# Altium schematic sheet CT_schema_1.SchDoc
size 684 x 556 mm
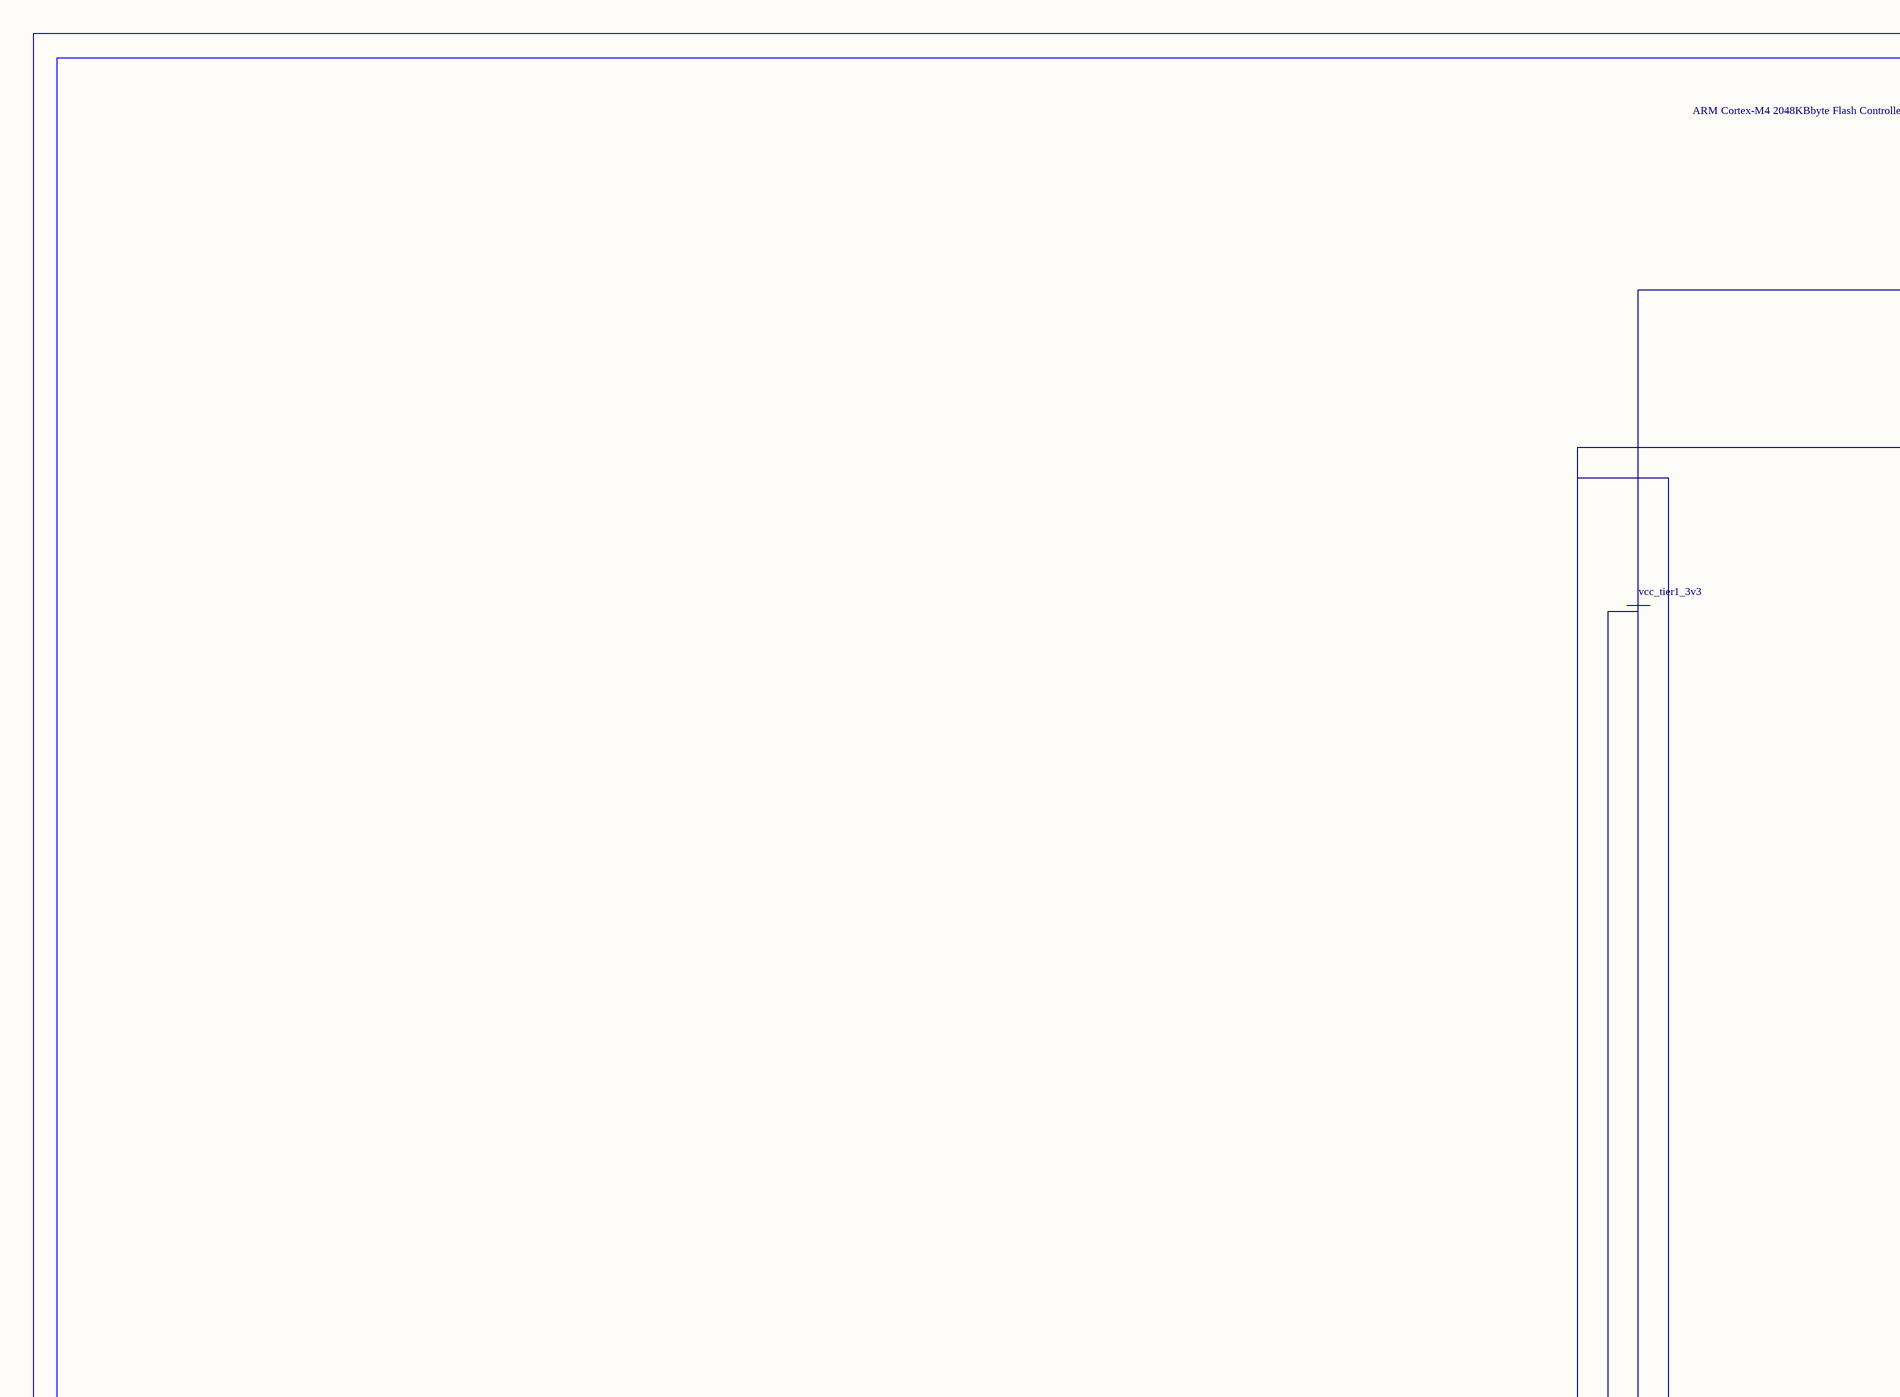
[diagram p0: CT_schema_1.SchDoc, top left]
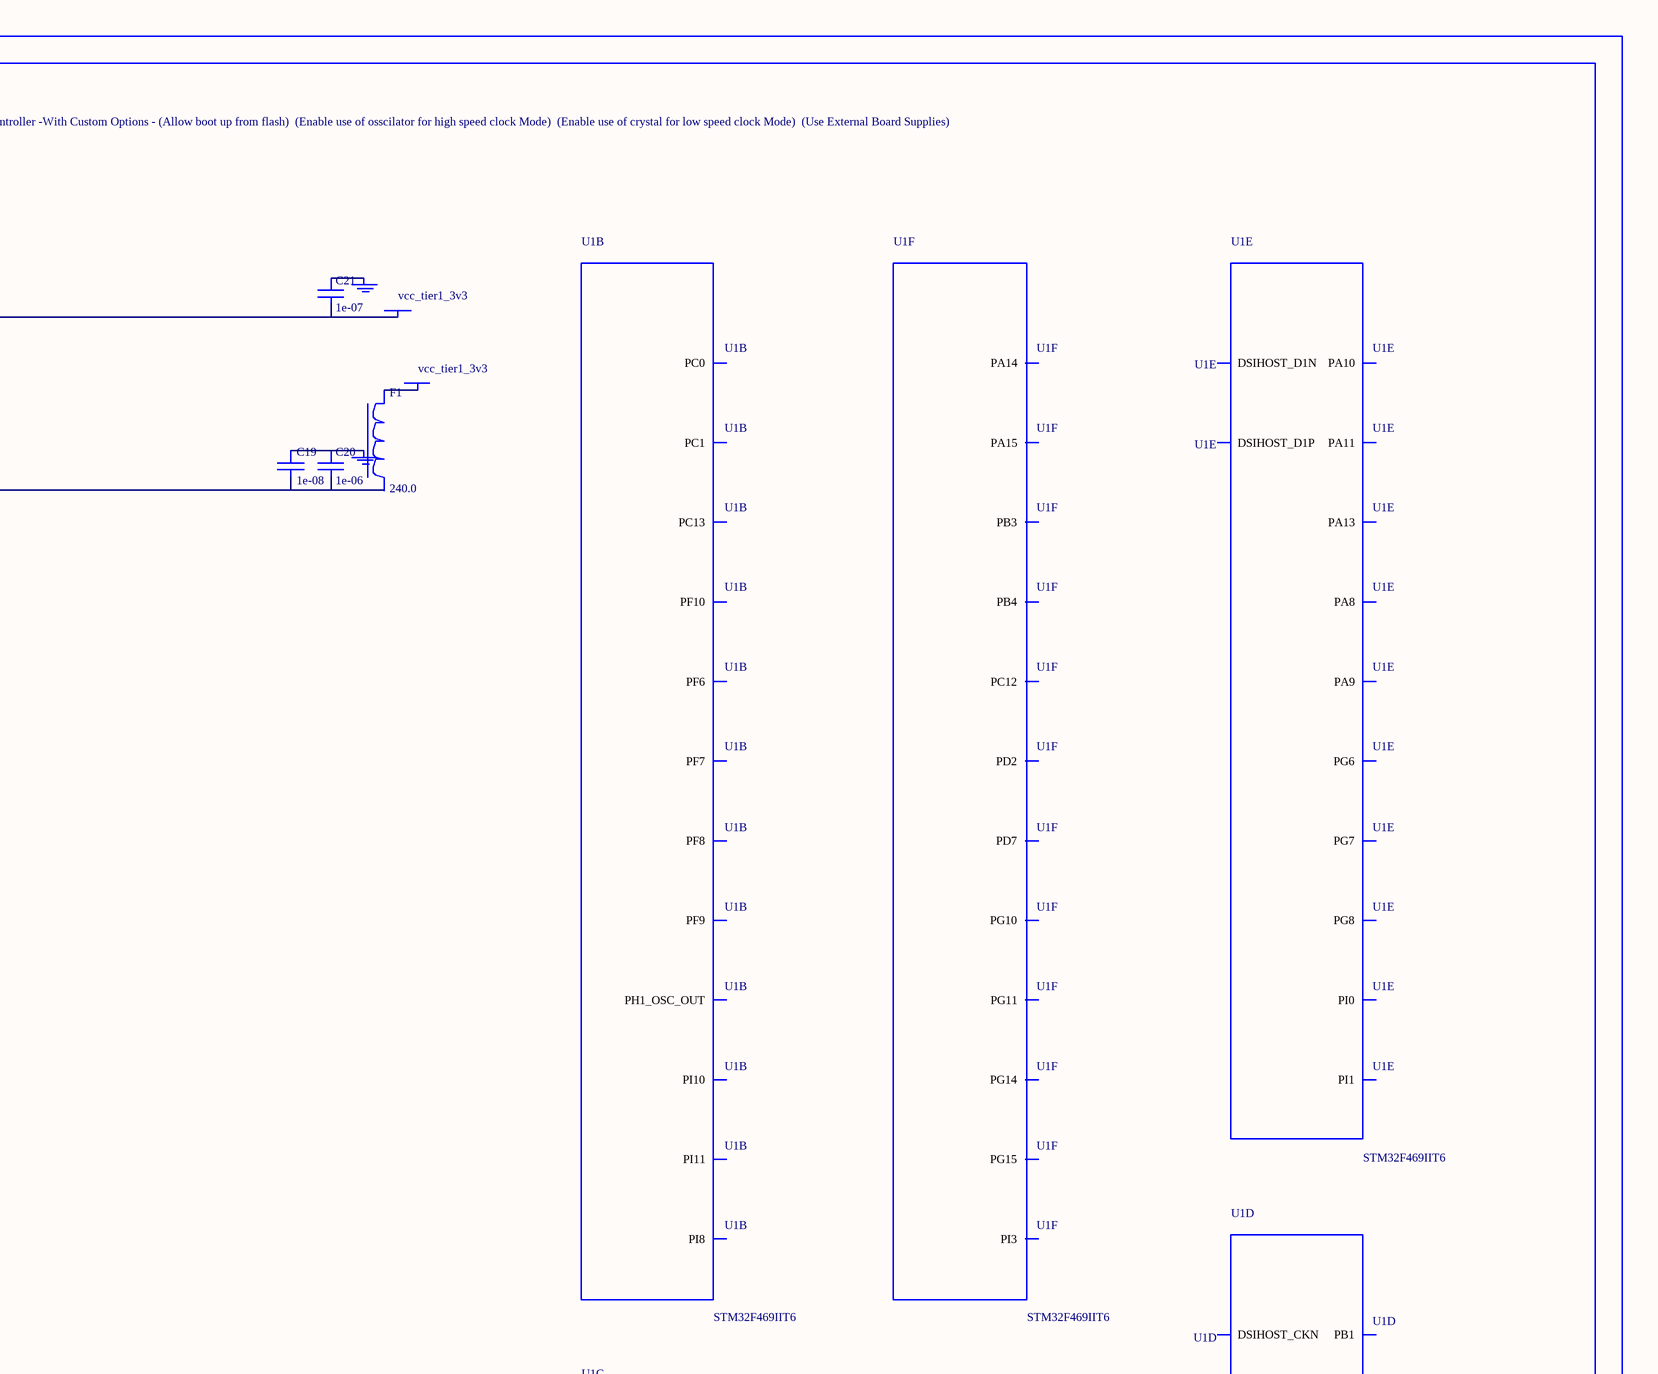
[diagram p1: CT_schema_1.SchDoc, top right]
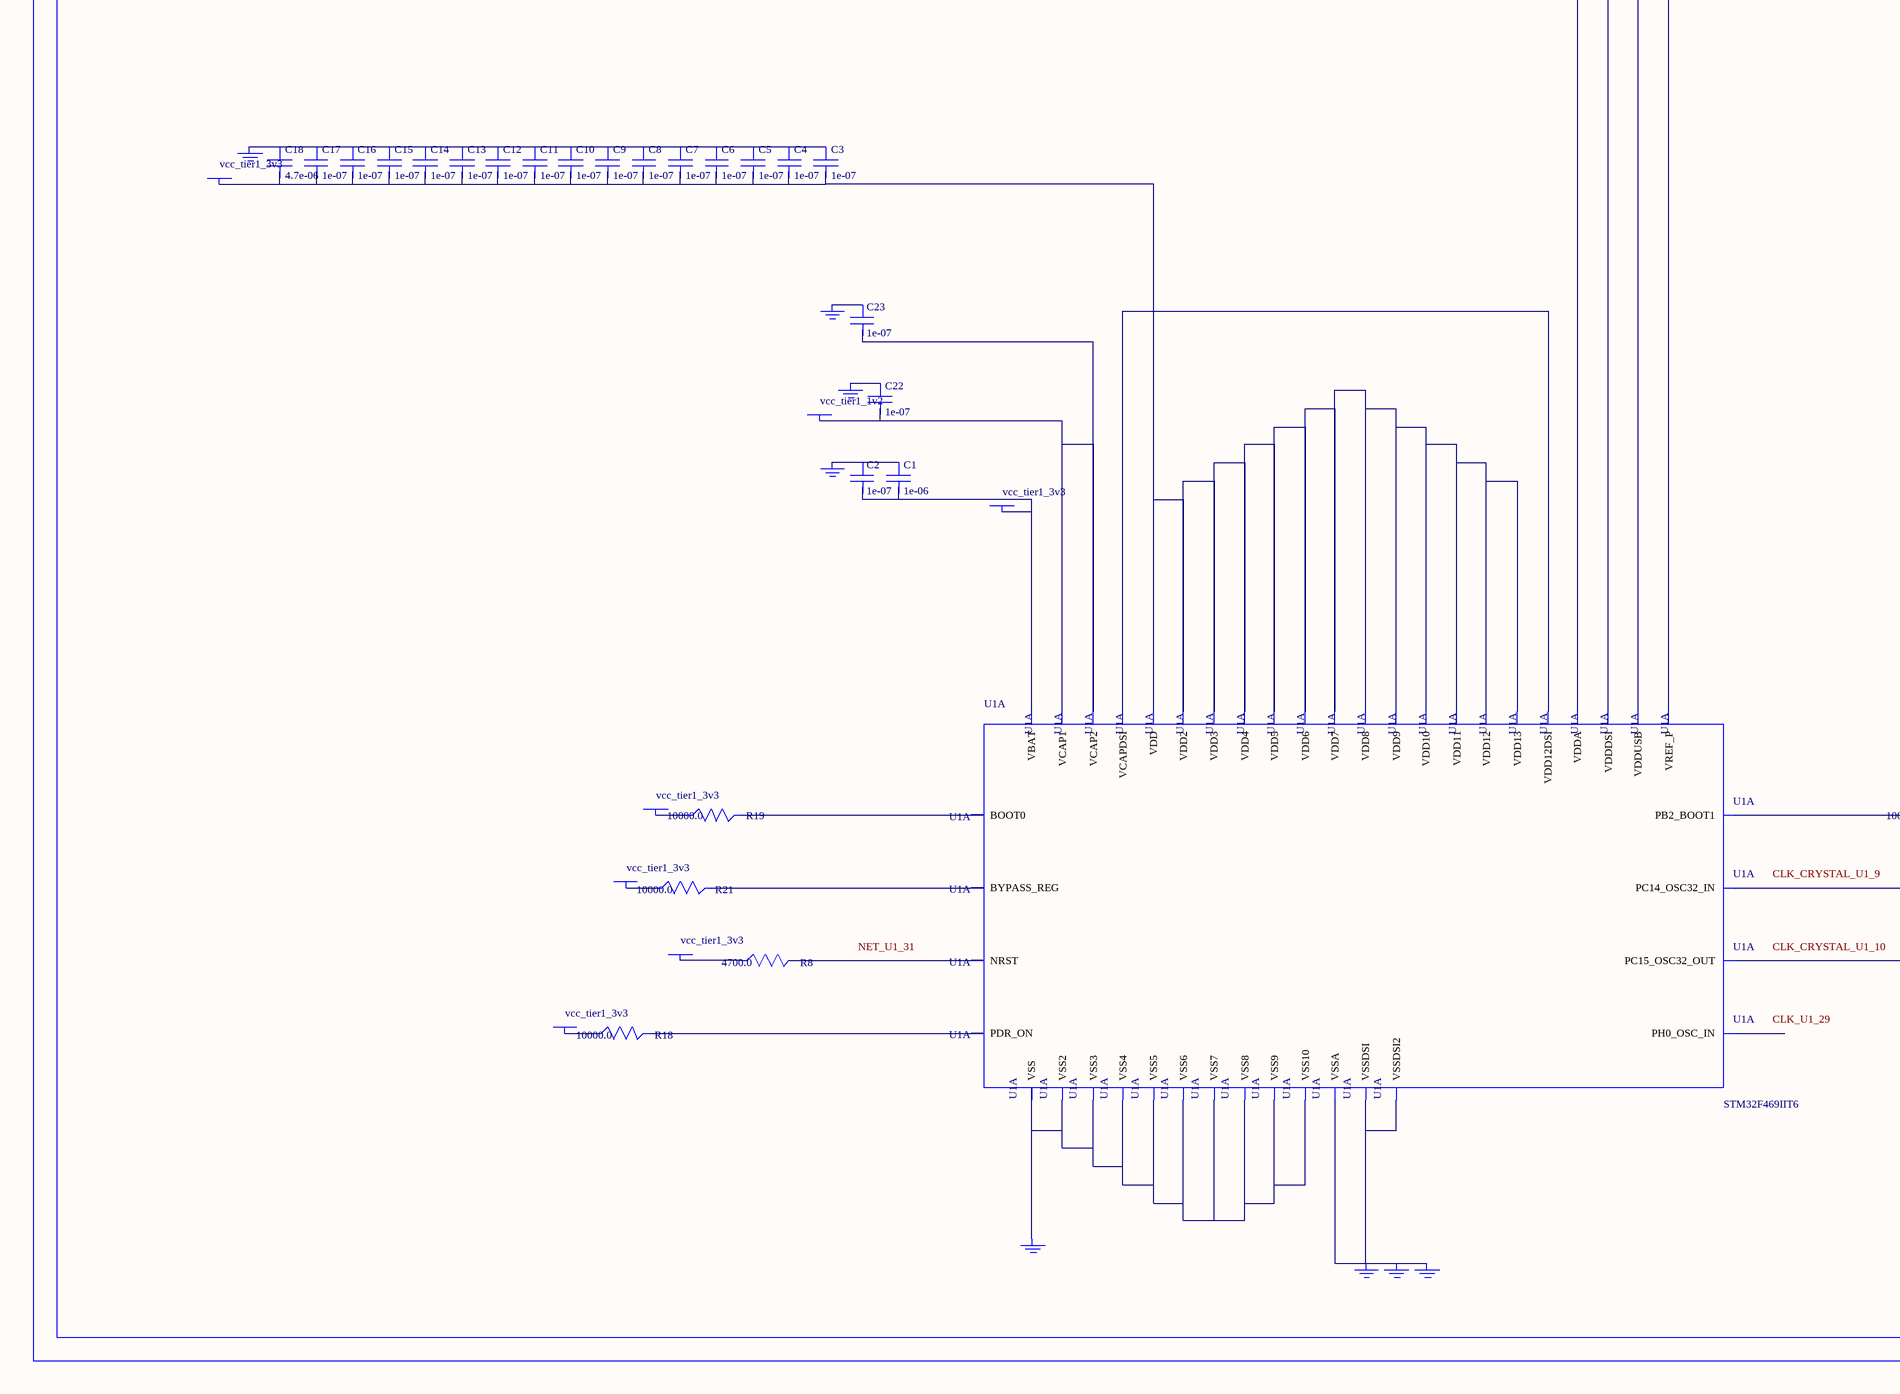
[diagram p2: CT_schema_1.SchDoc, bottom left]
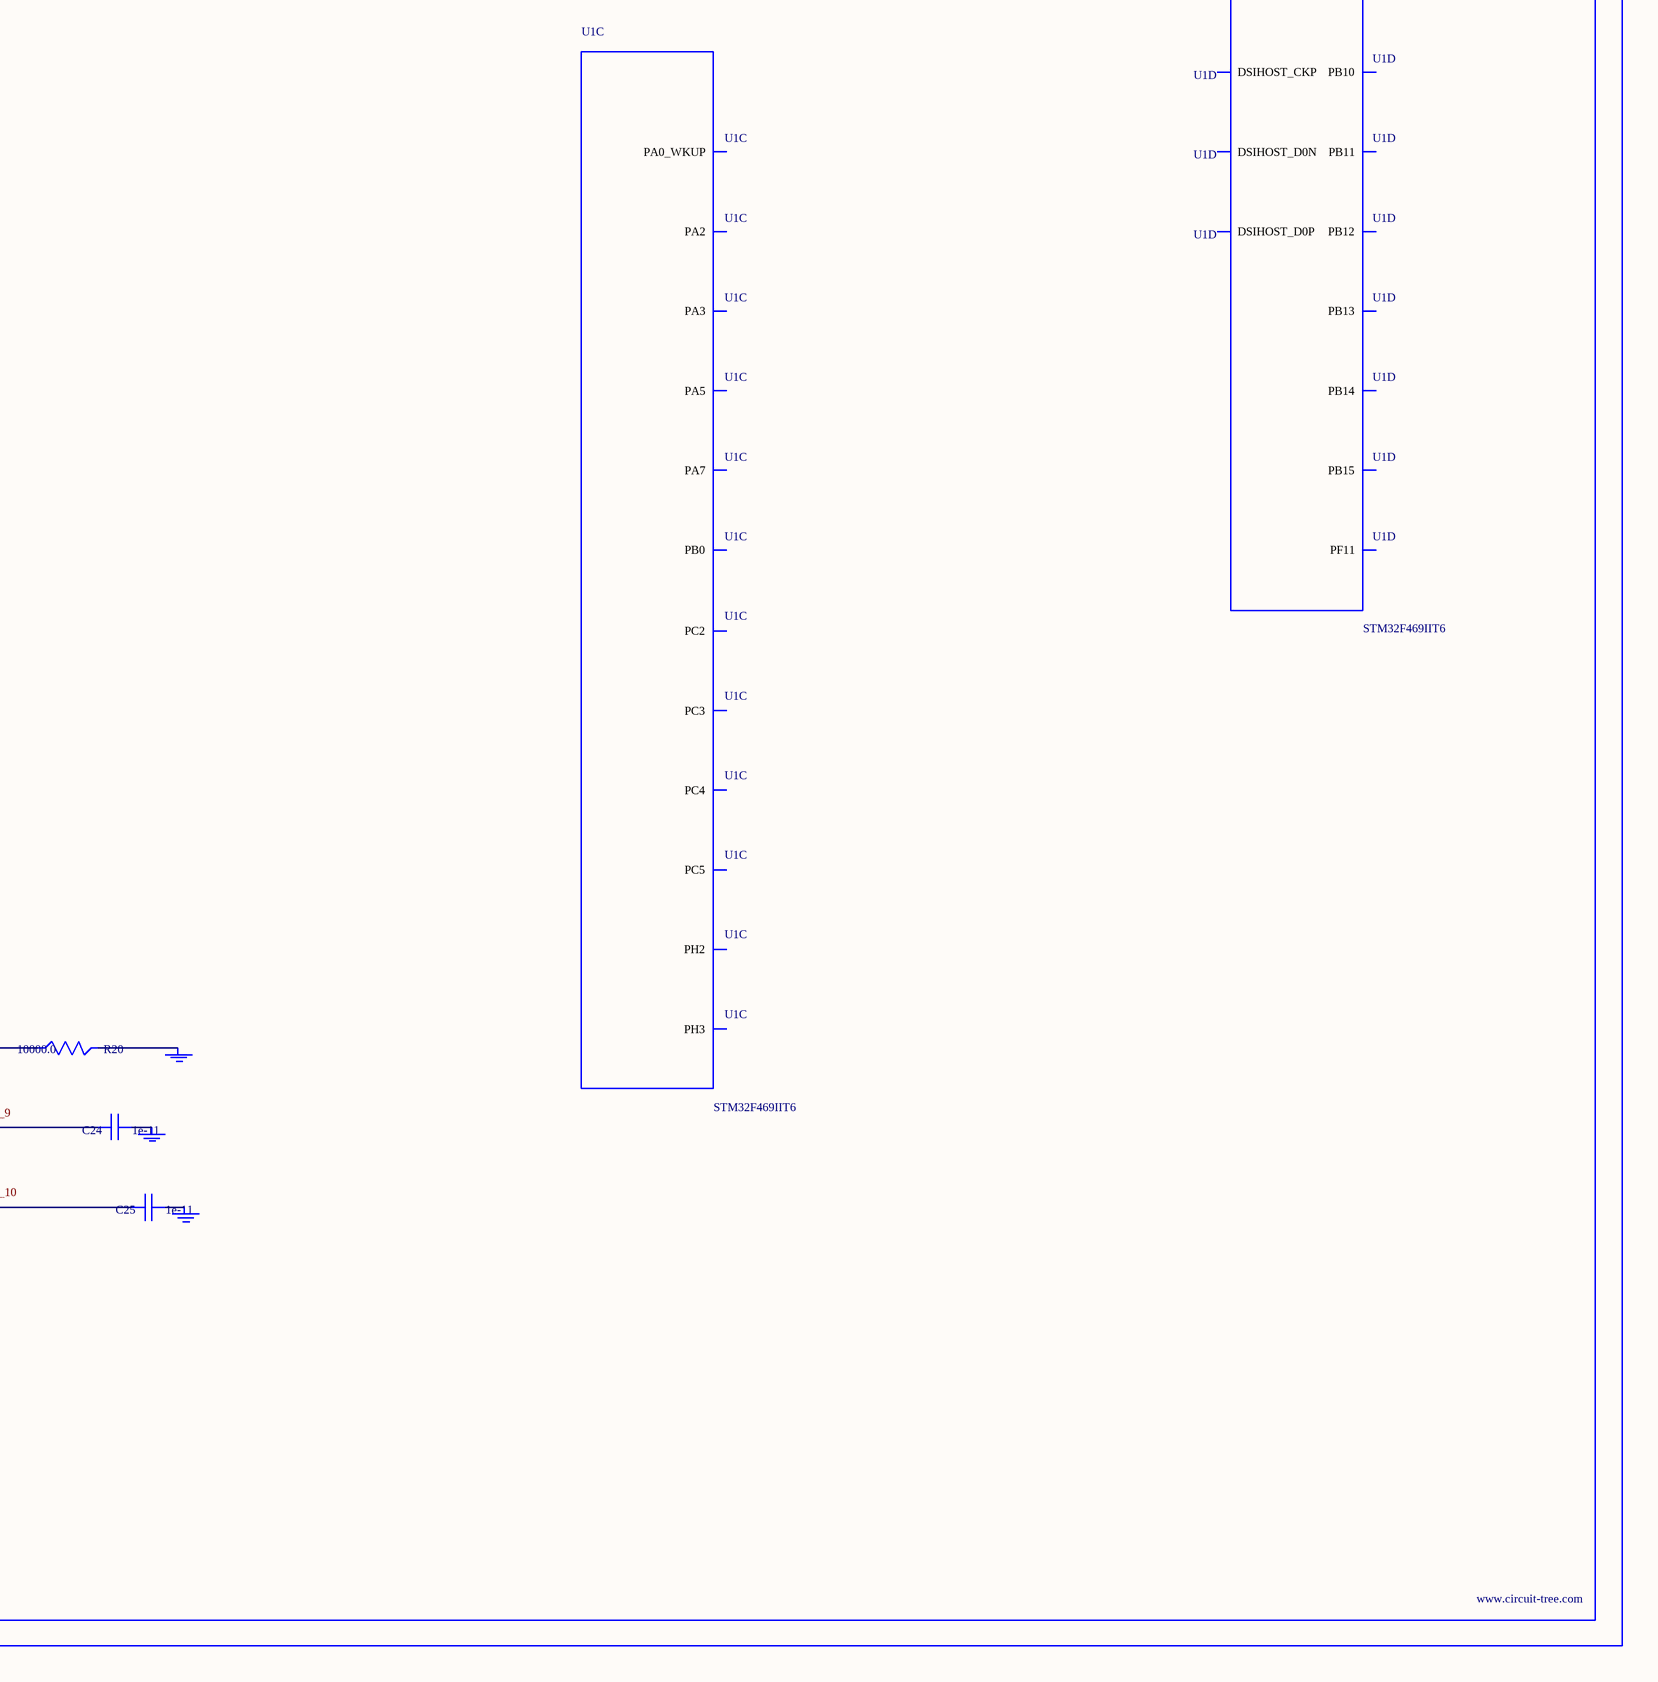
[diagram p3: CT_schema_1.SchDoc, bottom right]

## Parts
BORDER0  (no value)
C1  1e-06  [C0603]
C2  1e-07  [C0603]
C3  1e-07  [C0603]
C4  1e-07  [C0603]
C5  1e-07  [C0603]
C6  1e-07  [C0603]
C7  1e-07  [C0603]
C8  1e-07  [C0603]
C9  1e-07  [C0603]
C10  1e-07  [C0603]
C11  1e-07  [C0603]
C12  1e-07  [C0603]
C13  1e-07  [C0603]
C14  1e-07  [C0603]
C15  1e-07  [C0603]
C16  1e-07  [C0603]
C17  1e-07  [C0603]
C18  4.7e-06  [C0603]
C19  1e-08  [C0603]
C20  1e-06  [C0603]
C21  1e-07  [C0603]
C22  1e-07  [C0603]
C23  1e-07  [C0603]
C24  1e-11  [C0402]
C25  1e-11  [C0402]
F1  240.0  [L0603]
GND_INSTANCE_0_0  (no value)
GND_INSTANCE_0_1  (no value)
GND_INSTANCE_0_2  (no value)
GND_INSTANCE_0_3  (no value)
GND_INSTANCE_0_4  (no value)
GND_INSTANCE_0_5  (no value)
GND_INSTANCE_0_6  (no value)
GND_INSTANCE_0_7  (no value)
GND_INSTANCE_0_8  (no value)
GND_INSTANCE_0_9  (no value)
GND_INSTANCE_0_10  (no value)
GND_INSTANCE_0_11  (no value)
GND_INSTANCE_0_12  (no value)
POWER_INSTANCE_0_0  vcc_tier1_3v3
POWER_INSTANCE_0_1  vcc_tier1_3v3
POWER_INSTANCE_0_2  vcc_tier1_3v3
POWER_INSTANCE_0_3  vcc_tier1_3v3
POWER_INSTANCE_0_4  vcc_tier1_1v2
POWER_INSTANCE_0_5  vcc_tier1_3v3
POWER_INSTANCE_0_6  vcc_tier1_3v3
POWER_INSTANCE_0_7  vcc_tier1_3v3
POWER_INSTANCE_0_8  vcc_tier1_3v3
POWER_INSTANCE_0_9  vcc_tier1_3v3
R8  4700.0  [R0603]
R18  10000.0  [R0603]
R19  10000.0  [R0603]
R20  10000.0  [R0603]
R21  10000.0  [R0603]
U1  STM32F469IIT6  [LQFP176]  (parts A,B,C,D,E,F of 14)

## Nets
NetC1_1: C1.1 C2.1 GND_INSTANCE_0_0.0(GND)
NetC1_2: C1.2 C2.2 POWER_INSTANCE_0_0.0(PWR) U1.6(VBAT)
NetC3_1: C3.1 C4.1 C5.1 C6.1 C7.1 C8.1 C9.1 C10.1 C11.1 C12.1 C13.1 C14.1 C15.1 C16.1 C17.1 C18.1 GND_INSTANCE_0_3.0(GND)
NetC3_2: C3.2 C4.2 C5.2 C6.2 C7.2 C8.2 C9.2 C10.2 C11.2 C12.2 C13.2 C14.2 C15.2 C16.2 C17.2 C18.2 POWER_INSTANCE_0_1.0(PWR) U1.15(VDD) U1.23(VDD2) U1.36(VDD3) U1.49(VDD4) U1.62(VDD5) U1.72(VDD6) U1.82(VDD7) U1.96(VDD8) U1.131(VDD9) U1.136(VDD10) U1.149(VDD11) U1.159(VDD12) U1.172(VDD13)
NetC19_1: C19.1 C20.1 GND_INSTANCE_0_5.0(GND)
NetC19_2: C19.2 C20.2 U1.38(VREF_P) U1.39(VDDA)
NetC21_1: C21.1 GND_INSTANCE_0_10.0(GND)
NetC21_2: C21.2 POWER_INSTANCE_0_5.0(PWR) POWER_INSTANCE_0_6.0(PWR) U1.99(VDDDSI) U1.118(VDDUSB)
NetC22_1: C22.1 GND_INSTANCE_0_7.0(GND)
NetC22_2: C22.2 C23.2 POWER_INSTANCE_0_4.0(PWR) U1.81(VCAP1) U1.129(VCAP2)
NetC23_1: C23.1 GND_INSTANCE_0_11.0(GND)
NetC24_1: C24.1 GND_INSTANCE_0_1.0(GND)
NetC24_2: C24.2 U1.9(PC14_OSC32_IN)
NetC25_1: C25.1 GND_INSTANCE_0_2.0(GND)
NetC25_2: C25.2 U1.10(PC15_OSC32_OUT)
NetF1_1: F1.1 POWER_INSTANCE_0_2.0(PWR)
NetGND_INSTANCE_0_4_0: GND_INSTANCE_0_4.0(GND) GND_INSTANCE_0_8.0(GND) GND_INSTANCE_0_9.0(GND) U1.37(VSSA) U1.103(VSSDSI) U1.109(VSSDSI2)
NetGND_INSTANCE_0_6_0: GND_INSTANCE_0_6.0(GND) R20.2
NetGND_INSTANCE_0_12_0: GND_INSTANCE_0_12.0(GND) U1.14(VSS) U1.22(VSS2) U1.61(VSS3) U1.71(VSS4) U1.95(VSS5) U1.117(VSS6) U1.130(VSS7) U1.135(VSS8) U1.148(VSS9) U1.158(VSS10)
NetPOWER_INSTANCE_0_3_0: POWER_INSTANCE_0_3.0(PWR) R21.1
NetPOWER_INSTANCE_0_7_0: POWER_INSTANCE_0_7.0(PWR) R19.1
NetPOWER_INSTANCE_0_8_0: POWER_INSTANCE_0_8.0(PWR) R18.1
NetPOWER_INSTANCE_0_9_0: POWER_INSTANCE_0_9.0(PWR) R8.1
NetR8_2: R8.2 U1.31(NRST)
NetR18_2: R18.2 U1.171(PDR_ON)
NetR19_2: R19.2 U1.166(BOOT0)
NetR20_1: R20.1 U1.58(PB2_BOOT1)
NetR21_2: R21.2 U1.48(BYPASS_REG)
NetU1_100: U1.100(VCAPDSI) U1.106(VDD12DSI)

Not connected (* = marked no-connect by the designer): F1 2; U1 7(PI8) 8(PC13) 12(PI10) 13(PI11) 24(PF6) 25(PF7) 26(PF8) 27(PF9) 28(PF10) 29(PH0_OSC_IN) 30(PH1_OSC_OUT) 32(PC0) 33(PC1) 34(PC2) 35(PC3) 40(PA0_WKUP) 42(PA2) 43(PH2) 44(PH3) 47(PA3) 51(PA5) 53(PA7) 54(PC4) 55(PC5) 56(PB0) 57(PB1) 59(PF11) 79(PB10) 80(PB11) 85(PB12) 86(PB13) 87(PB14) 88(PB15) 101(DSIHOST_D0P) 102(DSIHOST_D0N) 104(DSIHOST_CKP) 105(DSIHOST_CKN) 107(DSIHOST_D1P) 108(DSIHOST_D1N) 114(PG6) 115(PG7) 116(PG8) 123(PA8) 124(PA9) 125(PA10) 126(PA11) 128(PA13) 132(PI0) 133(PI1) 134(PI3) 137(PA14) 138(PA15) 141(PC12) 144(PD2) 151(PD7) 153(PG10) 154(PG11) 157(PG14) 160(PG15) 161(PB3) 162(PB4)

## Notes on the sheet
- Labels drawn without touching a wire or pin: CLK_CRYSTAL_U1_9, CLK_CRYSTAL_U1_10, CLK_U1_29, NET_U1_31

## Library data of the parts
BORDER0 = BORDER_PAGE0
C1 C20 = C0603C105K3RACTU
C2-C17 C21-C23 = 06035C104K4Z2A
C18 = GRM188R6YA475KE15D
C19 = 06035C103K4Z2A
C24 C25 = C0402C100K3GACTU
F1 = Z0603C241ASMST
GND_INSTANCE_0_0-GND_INSTANCE_0_12 = GND
POWER_INSTANCE_0_0-POWER_INSTANCE_0_9 = PWR
R8 = RC0603JR-074K7L
R18-R21 = RC0603JR-0710KL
